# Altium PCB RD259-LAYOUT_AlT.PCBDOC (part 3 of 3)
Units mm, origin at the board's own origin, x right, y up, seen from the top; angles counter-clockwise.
Board outline 82.5 x 69.38 mm, 2 copper layers (TOP, BOTTOM), stack 0 mm thick; 80 components, 51 nets, 446 pads, 0 vias.
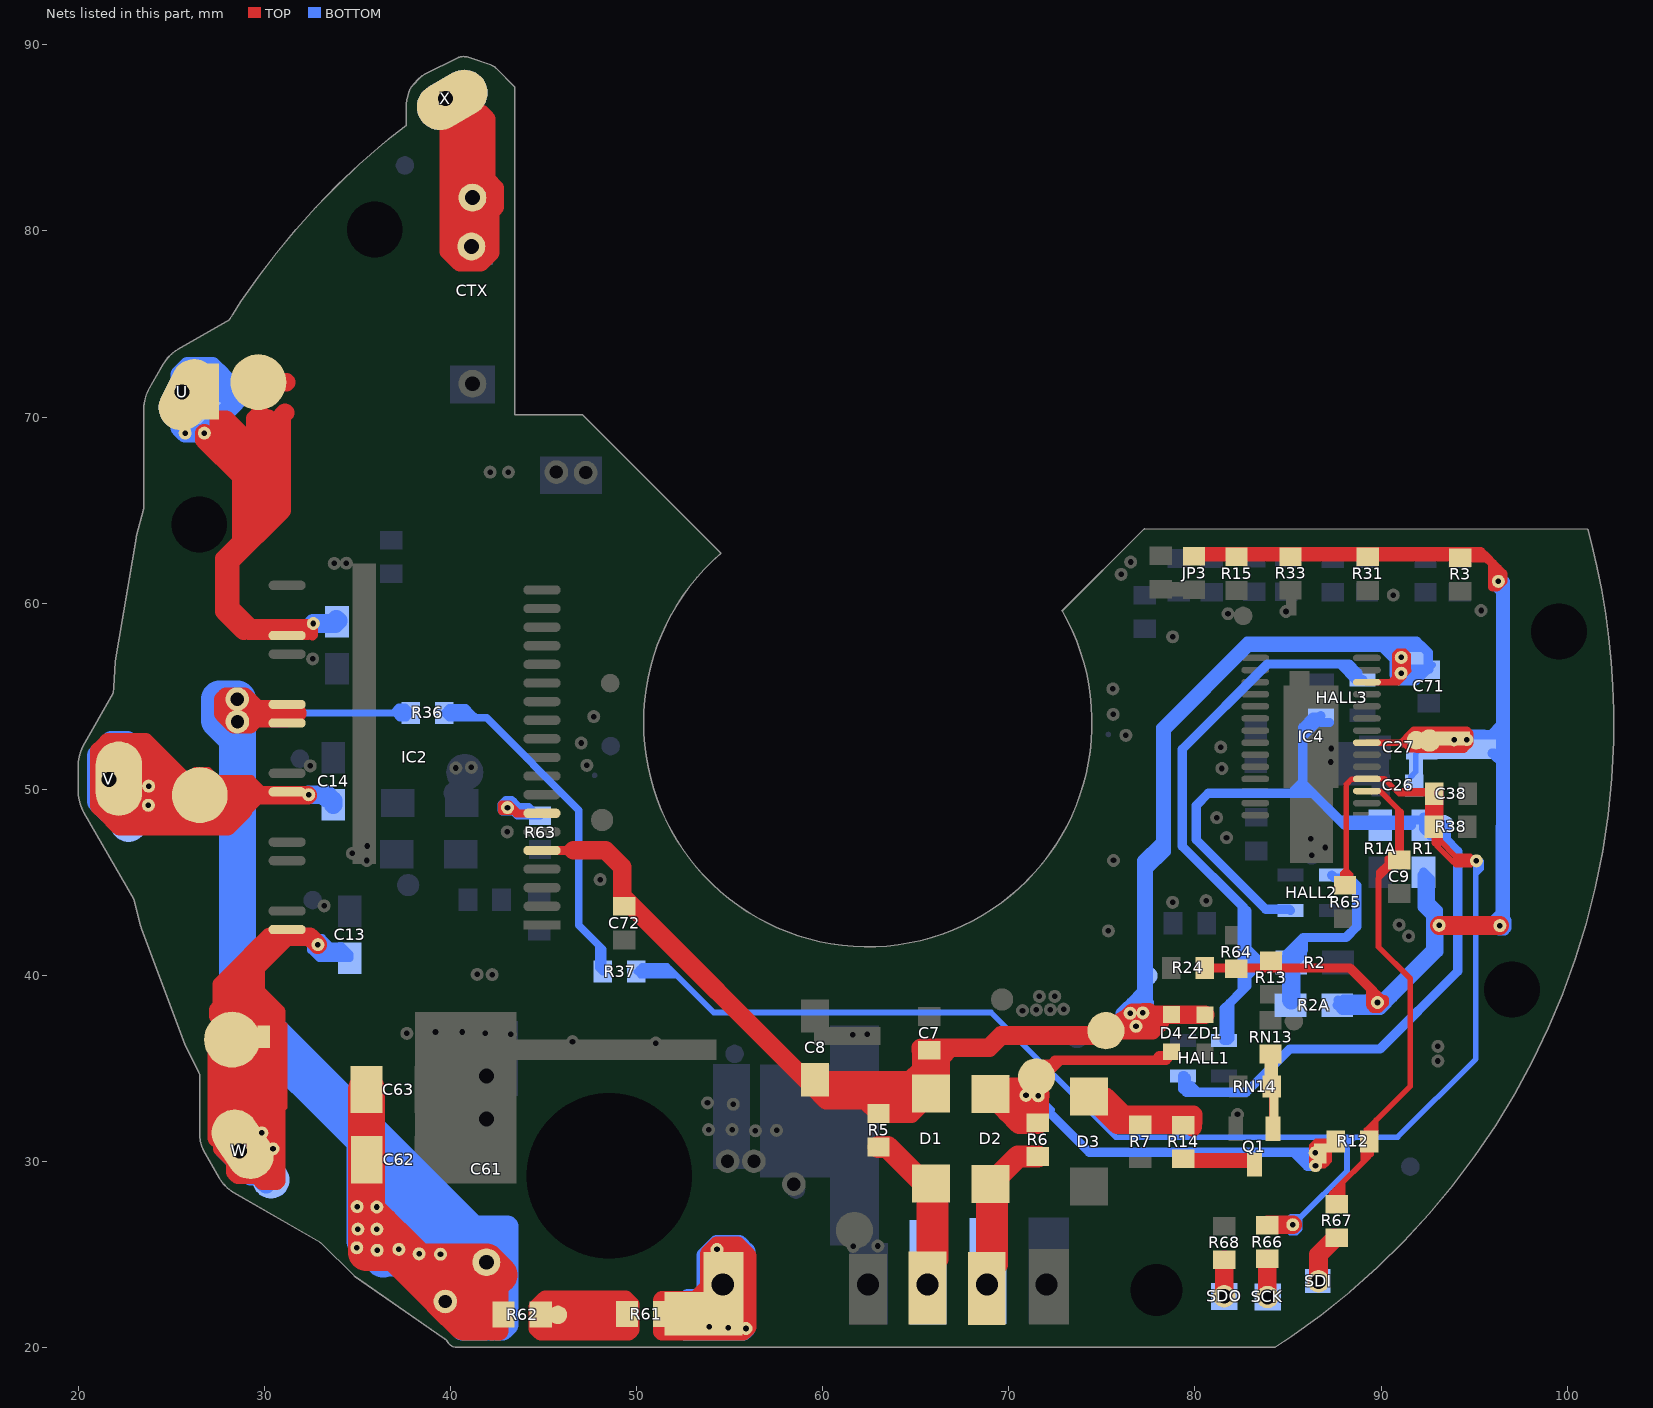
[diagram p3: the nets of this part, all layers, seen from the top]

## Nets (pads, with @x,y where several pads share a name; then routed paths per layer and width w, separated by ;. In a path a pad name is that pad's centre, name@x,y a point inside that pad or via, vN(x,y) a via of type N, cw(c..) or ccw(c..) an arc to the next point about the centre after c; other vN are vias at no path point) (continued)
NetD2_2: D2.2 D4.1 pad.@70.92,33.547 pad.@71.198,33.417 pad.@71.235,32.547 pad.@71.491,34.541 pad.@71.579,33.525 pad.@86.48,29.77 pad.@86.74,30.424 pad.@86.456,30.455 R6.2 R12.1 | length 57.1
  TOP w0.3: pad.@86.48,29.77 86.492,29.759 86.946,29.759 pad.@87.084,29.897 ; pad.@86.48,29.77 86.468,29.782 86.468,30.442 pad.@86.456,30.455 86.564,30.455 86.637,30.527 86.726,30.616 pad.@87.041,30.616 ; pad.@86.48,29.77 86.458,29.77 86.282,29.946 86.282,30.455 86.282,30.838 86.304,30.86 86.511,31.066 87.041,31.066 ; pad.@87.041,30.616 87.041,31.066 ; pad.@87.041,30.616 87.041,29.939 pad.@87.084,29.897 ; pad.@87.041,30.616 R12.1@87.222,30.616 ; 87.041,31.066 R12.1@87.572,31.066 ; pad.@87.084,29.897 87.176,29.989 87.222,30.035 R12.1@87.222,30.616 ; R12.1@87.222,30.616 87.222,30.716 R12.1@87.572,31.066 ; R12.1@87.222,30.616 87.572,30.966 R12.1@87.572,31.066
  TOP w0.5: 70.054,34.198 70.111,34.254 71.204,34.254 71.338,34.388 pad.@71.491,34.541 71.897,34.541 72.789,35.433 ; pad.@71.95,35.213 72.25,35.213 72.47,35.433 72.789,35.433 ; D4.1@78.47,35.555 78.348,35.433 ; D4.1@78.747,35.886 D4.1@78.547,35.686 ; 72.789,35.433 77.836,35.433 ; 77.836,35.433 78.088,35.686 D4.1@78.547,35.686 ; 77.836,35.433 78.348,35.433 ; 78.348,35.433 78.454,35.433 78.547,35.526 D4.1@78.547,35.686
  TOP w1.2: D2.2@69.021,33.615 D2.2@69.089,33.547 ; pad.@70.92,33.547 D2.2@69.089,33.547 ; pad.@71.338,34.388 71.338,32.83 71.202,32.693 ; pad.@71.356,33.591 pad.@71.513,33.591 ; pad.@71.579,33.591 pad.@71.513,33.591 ; D2.2@69.089,33.547 D2.2@69.943,32.693 ; D2.2@69.943,32.693 71.202,32.693 ; D2.2@69.943,32.693 70.572,32.064 ; 70.572,32.064 71.202,32.693 ; 70.572,32.064 R6.2@71.549,32.064 71.549,32.83 ; 71.202,32.693 71.413,32.693 71.549,32.83 ; pad.@71.513,33.591 pad.@71.579,33.525 71.549,33.495 71.549,32.83
  BOTTOM w0.3: pad.@70.92,33.547 70.931,33.536 71.568,33.536 71.919,33.184 ; pad.@71.153,33.047 71.197,33.003 71.785,33.003 71.801,33.003 71.986,32.819 ; pad.@71.235,32.547 71.323,32.635 72.17,32.635 ; 71.919,33.184 71.919,33.767 71.744,33.943 70.983,33.943 70.977,33.948 70.73,33.948 70.494,33.712 70.494,33.366 70.616,33.244 70.821,33.039 71.041,32.819 71.986,32.819 ; 71.919,33.184 72.327,32.777 72.185,32.635 72.17,32.635 ; 71.986,32.819 72.17,32.635
  BOTTOM w0.5: 72.17,32.635 74.313,30.491 85.281,30.491 ; 85.281,30.491 85.85,30.491 ; 85.281,30.491 86.034,29.738 86.448,29.738 pad.@86.48,29.77 ; 85.85,30.491 86.419,30.491 pad.@86.456,30.455 86.468,30.442 pad.@86.468,29.837 ; 85.85,30.491 85.85,30.455 pad.@86.468,29.837 ; pad.@86.468,29.837 86.48,29.824 pad.@86.48,29.77 ; pad.@86.468,29.837 86.468,29.782 pad.@86.48,29.77
NetD3_2: D3.2 R7.2 R14.1 | length 12.7
  TOP w1: R14.1@79.883,31.847 79.772,31.958 R7.2@77.062,31.958 75.827,31.958 D3.2@74.306,33.479 75.2,33.479 76.17,32.509 79.901,32.509 R14.1@79.901,32.086
NetHALL1_1: HALL1.1 HALL2.1 HALL3.1 pad.@82.784,40.451 R2.1 R2A.1 | length 57.1
  BOTTOM w0.5: R2.1@84.968,41.165 85.399,41.595 ; R2.1@85.077,40.451 83.3,40.451 ; HALL2.1@87.359,45.383 87.512,45.23 88.293,45.23 88.695,44.829 88.695,42.604 88.116,42.025 85.829,42.025 ; HALL3.1@89.012,55.874 HALL3.1@88.856,55.874 ; 81.865,38.5 81.573,38.209 HALL1.1@81.573,36.497 81.765,36.497 81.865,36.597 81.865,38.5 ; 81.865,38.5 82.527,39.163 ; 82.527,39.163 82.527,43.729 ; 82.527,39.163 82.784,39.419 82.784,39.935 ; 82.527,43.729 79.326,46.93 79.326,52.153 83.899,56.726 87.81,56.726 ; 82.527,43.729 82.784,43.472 82.784,41.445 ; 82.784,39.935 83.042,40.193 83.3,40.451 ; 82.784,39.935 pad.@82.784,40.451 ; pad.@82.784,40.451 82.784,40.837 ; pad.@82.784,40.451 83.3,40.451 ; 82.784,40.837 83.392,40.837 ; 82.784,40.837 82.784,41.445 ; 82.784,41.445 83.392,40.837 ; 83.392,40.837 85.019,40.837 R2.1@85.171,40.685 ; R2.1@85.171,40.685 85.386,40.685 85.771,41.07 85.771,41.285 85.829,41.343 85.829,42.025 ; R2.1@85.171,40.685 85.399,40.912 85.399,41.595 ; 85.399,41.595 85.829,42.025 ; 87.81,56.726 88.292,56.726 88.756,56.262 88.756,55.974 HALL3.1@88.856,55.874 ; 87.81,56.726 88.662,55.874 HALL3.1@88.856,55.874
  BOTTOM w1: R2A.1@85.171,38.668 R2.1@85.171,40.685
NetHALL1_3: HALL1.3 HALL2.3 HALL3.3 pad.@93.405,48.107 R1.2 R1A.2 | length 65.9
  BOTTOM w0.5: HALL2.3@85.134,43.483 85.07,43.547 83.808,43.547 80.071,47.284 80.071,49.126 80.722,49.776 85.185,49.776 ; 86.493,53.528 85.796,52.831 ; 86.761,53.589 87.232,53.589 ; HALL3.3@86.767,53.953 86.687,53.874 86.337,53.874 85.796,53.333 85.796,52.831 ; 91.637,48.052 R1A.2@89.963,48.052 88.062,48.052 87.773,48.34 ; R1.2@92.283,48.052 92.283,47.887 92.668,47.502 93.291,47.502 ; R1.2@92.292,48.5 R1.2@92.452,48.34 ; 79.531,33.707 79.348,33.89 HALL1.3@79.348,34.597 79.431,34.597 79.531,34.497 79.531,34.057 ; 79.531,33.707 79.531,34.057 ; 79.531,33.707 80.148,33.707 ; 79.531,34.057 79.798,34.057 80.148,33.707 ; 80.148,33.707 82.765,33.707 85.091,36.033 89.95,36.033 94.13,40.213 94.13,46.663 93.501,47.292 ; 85.185,49.776 85.727,50.318 85.796,50.318 ; 85.185,49.776 85.796,49.776 ; 85.796,49.776 85.796,50.318 ; 85.796,49.776 86.337,49.776 ; 85.796,50.318 85.796,52.831 ; 85.796,50.318 86.337,49.776 ; 86.337,49.776 87.773,48.34 ; 87.773,48.34 R1.2@92.452,48.34 ; R1.2@92.452,48.34 92.511,48.281 93.046,47.747 93.291,47.502 ; R1.2@92.452,48.34 93.037,48.34 93.27,48.107 pad.@93.405,48.107 93.501,48.011 93.501,47.292 ; 93.291,47.502 93.501,47.292
NetQ1_1: pad.@84.108,35.099 pad.@84.247,32.965 Q1.1 RN13.2 RN14.1 | length 4.1
  TOP w0.3: RN13.2@84.064,35.77 84.064,34.078 RN14.1@84.122,34.02 ; RN14.1@84.144,33.998 RN14.1@84.122,34.02 ; Q1.1@84.196,31.749 84.122,31.824 RN14.1@84.122,34.02
NetQ1_2: Q1.2 R14.2 | length 3.3
  TOP w0.8: R14.2@79.883,30.044 Q1.2@83.187,30.044
NetR36_2: R36.2 R37.1 | length 23.6
  BOTTOM w0.4: R36.2@39.655,54.095 41.081,54.095 ; R36.2@39.655,54.095 39.927,54.367 40.809,54.367 41.081,54.095 ; R36.2@39.655,54.095 39.915,53.835 41.341,53.835 ; 41.081,54.095 41.341,53.835 ; 41.341,53.835 41.936,53.835 46.895,48.876 46.895,42.689 47.97,41.614 ; 47.97,41.614 48.177,41.407 R37.1@48.177,40.199 47.97,40.406 47.97,41.614
NetR61_2: pad.@45.764,21.749 R61.2 R62.1 | length 16.9
  TOP w1: 46.059,22.561 45.102,22.561 44.692,22.151 44.692,21.032 44.863,20.862 49.538,20.862 49.646,20.969 49.646,22.284 49.377,22.553 45.678,22.553 45.506,22.381 45.506,22.007 pad.@45.764,21.749 48.602,21.749
RES: C38.2 IC4.4 pad.@85.259,26.594 pad.@95.129,46.15 R37.2 R38.2 R65.1 R66.1 | length 104.2
  TOP w0.3: R66.1@83.889,26.563 R66.1@83.92,26.594 ; R65.1@88.146,45.096 88.142,45.1 88.142,45.634 ; R38.2@92.837,47.983 R38.2@92.867,47.954 ; R38.2@92.858,47.983 92.867,47.974 R38.2@92.867,47.954 ; 93.285,47.114 93.187,47.211 ; 94.787,46.391 94.007,46.391 93.187,47.211 ; 94.832,45.944 94.032,45.944 93.826,46.15 ; pad.@95.129,46.15 93.826,46.15 ; 88.142,45.634 88.142,45.67 ; 88.142,45.634 88.38,45.396 88.38,45.147 R65.1@88.066,44.833 87.945,44.954 87.945,45.473 88.142,45.67 ; 88.142,45.67 88.142,50.264 88.42,50.542 89.232,50.542 IC4.4@89.242,50.552 90.186,50.552 90.813,49.925 ; 90.813,49.925 90.99,49.748 C38.2@92.858,49.748 92.681,49.925 90.813,49.925 ; R38.2@92.867,47.954 R38.2@93.072,47.749 ; R38.2@92.867,47.954 92.867,47.109 93.072,46.904 ; 93.072,46.904 93.072,47.326 ; 93.072,46.904 93.826,46.15 ; 93.072,47.326 R38.2@93.072,47.749 ; 93.072,47.326 93.187,47.211 ; R38.2@93.072,47.749 93.187,47.633 93.187,47.211
  TOP w1: R66.1@83.92,26.594 pad.@85.259,26.594 ; R38.2@92.858,47.983 C38.2@92.858,49.748
  BOTTOM w0.3: 84.941,26.803 84.973,26.835 ; pad.@85.259,26.594 85.277,26.594 85.643,26.96 ; pad.@95.101,46.15 95.101,45.444 ; pad.@95.386,46.118 95.386,45.729 95.101,45.444 ; R37.2@49.98,40.199 51.938,40.199 ; R37.2@49.98,40.199 50.197,39.983 52.155,39.983 ; R37.2@49.98,40.199 R37.2@50.133,40.352 ; R37.2@50.133,40.352 51.785,40.352 ; R37.2@50.133,40.352 50.286,40.505 51.632,40.505 51.785,40.352 ; 51.785,40.352 51.938,40.199 ; 51.938,40.199 52.155,39.983 ; 52.155,39.983 54.139,37.998 69.046,37.998 75.747,31.298 87.769,31.298 ; 84.973,26.835 84.973,26.337 84.967,26.33 84.981,26.316 85.12,26.177 85.452,26.177 85.564,26.289 85.643,26.368 85.643,26.96 ; 84.973,26.835 84.973,26.841 85.163,27.031 85.715,27.031 ; 85.643,26.96 85.715,27.031 ; 85.715,27.031 88.171,29.487 88.171,30.933 ; 87.769,31.298 88.134,30.933 88.171,30.933 ; 87.769,31.298 88.171,31.298 ; 88.171,30.933 88.171,31.298 ; 88.171,30.933 88.228,30.933 88.593,31.298 ; 88.171,31.298 88.593,31.298 ; 88.593,31.298 90.896,31.298 95.101,35.503 95.101,45.444
SCK: pad.@83.916,22.699 R66.2 SCK.1 | length 2.1
  TOP w1: R66.2@83.889,24.759 83.894,24.759 83.894,22.715 SCK.1@83.898,22.711
SD: IC2.7 pad.@43.055,49.011 R63.1 | length 12.6
  TOP w0.4: pad.@43.055,49.011 pad.@43.263,48.803 ; 43.513,48.687 44.892,48.687 IC2.7@44.911,48.706 43.636,48.706 43.539,48.803 ; pad.@43.263,48.803 42.753,48.803 42.753,49.19 42.765,49.202 43.14,49.202 43.194,49.149 43.539,48.803 ; pad.@43.263,48.803 43.539,48.803
  BOTTOM w0.4: pad.@42.974,49.011 pad.@43.055,49.011 ; pad.@43.055,49.011 43.137,49.011 43.363,48.785 ; pad.@43.055,49.011 43.113,49.068 43.657,49.068 ; 43.363,48.785 42.784,48.785 42.714,48.855 42.714,49.195 42.793,49.274 42.948,49.429 43.296,49.429 43.385,49.34 43.657,49.068 ; 43.363,48.785 44.423,48.785 R63.1@44.454,48.815 ; 43.363,48.785 43.589,48.558 44.802,48.558 R63.1@44.806,48.563 44.706,48.563 R63.1@44.454,48.815 ; 43.657,49.068 44.201,49.068 R63.1@44.454,48.815
SDI: pad.@86.606,23.574 R67.2 SDI.1 | length 2.7
  TOP w1: SDI.1@86.641,23.552 86.641,24.978 87.515,25.853 R67.2@87.515,25.895
SDO: pad.@81.576,22.744 R68.2 SDO.1 | length 2
  TOP w1: R68.2@81.57,24.71 81.573,24.71 81.573,22.75 SDO.1@81.576,22.747
TX: CTX.2 pad.@40.084,87.046 pad.@41.13,80.653 pad.@41.114,79.17 X.1 | length 36.1
  TOP w0.5: pad.@41.114,79.17 pad.@41.169,79.224
  TOP w1: X.1@39.718,87.112 pad.@39.96,87.112 ; pad.@39.784,86.894 41.169,85.51 ; 40.137,85.621 39.914,85.398 39.914,80.234 ; CTX.2@41.114,81.735 CTX.2@41.169,81.79 ; pad.@41.169,79.224 pad.@41.169,79.36 ; pad.@41.191,79.29 pad.@41.191,79.382 ; 41.631,86.297 41.924,86.004 41.924,82.731 42.017,82.639 42.369,82.287 42.369,81.293 42.129,81.053 ; 39.914,80.234 39.914,78.91 40.384,78.44 40.507,78.317 41.605,78.317 41.786,78.498 42.129,78.841 42.129,81.053 ; 39.914,80.234 40.446,79.702 ; 40.446,79.702 40.446,84.788 41.169,85.51 ; 40.446,79.702 40.979,79.17 pad.@41.114,79.17 41.114,79.305 pad.@41.169,79.36 ; pad.@41.169,79.36 pad.@41.191,79.382 ; pad.@41.169,79.36 CTX.2@41.169,81.79 ; CTX.2@41.169,81.79 41.169,85.51 ; pad.@41.191,79.382 42.077,80.269 42.077,81.002 42.129,81.053
U: ?.1 IC2.21 pad.@25.89,71.194 pad.@25.733,69.135 pad.@26.274,71.063 pad.@26.765,69.135 pad.@27.051,71.37 pad.@27.848,71.222 pad.@29.666,71.876 pad.@32.623,58.906 U.1 | length 78
  TOP w0.4: 28.877,58.506 32.011,58.506 32.354,58.849 32.566,58.849 32.617,58.9 pad.@32.623,58.906
  TOP w0.5: 28.147,60.079 28.173,60.079 29.346,58.906 ; 28.478,58.906 29.346,58.906 ; 28.877,58.506 29.127,58.256 IC2.21@31.211,58.256 32.33,58.256 32.33,58.559 pad.@32.617,58.846 ; 32.581,58.254 32.617,58.29 pad.@32.617,58.846 ; pad.@32.617,58.9 pad.@32.617,58.846 ; 29.346,58.906 pad.@32.623,58.906 32.623,58.852 pad.@32.617,58.846
  TOP w1: pad.@26.765,69.135 26.765,68.785 28.741,66.81 ; 28.877,58.506 28.478,58.906 28.147,59.237 ; pad.@29.666,71.876 31.168,71.876 ; 29.769,70.173 29.514,69.918 29.514,68.271 ; 30.205,69.907 30.232,69.879 30.232,64.757 ; 31.1,70.221 30.93,70.052 30.93,65.456 ; 28.147,59.237 28.147,60.079 28.147,62.214 ; 28.147,59.237 27.831,59.553 27.831,62.375 28.147,62.691 ; 28.147,62.214 30.93,64.998 30.93,65.456 ; 28.147,62.214 28.147,62.691 ; 28.147,62.691 28.741,63.285 ; 28.741,63.285 29.055,63.599 ; 28.741,63.285 28.741,66.81 ; 28.741,66.81 29.055,66.495 ; 29.055,63.599 29.514,64.059 ; 29.055,63.599 29.055,66.495 ; 29.055,66.495 29.514,66.036 ; 29.514,64.059 29.533,64.059 30.232,64.757 ; 29.514,64.059 29.514,66.036 ; 29.514,66.036 29.514,67.342 ; 29.514,67.342 27.546,69.31 27.546,69.859 27.926,69.859 29.514,68.271 ; 29.514,67.342 29.514,68.271 ; 30.232,64.757 30.93,65.456
  BOTTOM w1: pad.@27.848,71.222 27.848,72.062 27.56,72.35 27.303,72.607 27.195,72.715 25.873,72.715 25.443,72.284 25.443,71.338 25.443,69.426 pad.@25.733,69.135 26.274,69.135 pad.@26.765,69.135 27.483,69.854 28.35,70.72 28.455,70.825 pad.@28.455,71.332 ; pad.@32.623,58.906 33.807,58.906 ?.1@33.894,58.993 33.945,59.043 ?.1@33.861,59.127
V: C14.1 IC2.26 pad.@22.173,50.564 pad.@22.259,50.494 pad.@22.693,48.165 pad.@23.77,50.165 pad.@23.755,49.135 pad.@26.522,49.681 pad.@32.376,49.702 V.1 | length 83.3
  TOP w0.4: pad.@22.173,50.564 pad.@22.63,50.106 ; pad.@26.274,51.002 26.987,51.002 27.435,50.554 29.273,50.554 29.613,50.215 ; pad.@26.522,49.681 26.339,50.215 29.613,50.215 ; 28.545,48.858 28.857,48.858 29.169,48.858 29.992,49.681 30.069,49.758 ; 29.106,49.875 29.952,49.875 ; 30.193,49.875 29.952,49.875 ; IC2.26@31.192,49.875 IC2.26@31.211,49.856 31.229,49.856 31.275,49.81 31.275,49.803 31.396,49.681 31.509,49.568 32.182,49.568 32.213,49.538 pad.@32.346,49.405 ; IC2.26@32.16,49.837 32.255,49.741 pad.@32.376,49.741 ; 29.613,50.215 29.952,49.875
  TOP w0.5: 30.193,49.875 IC2.26@31.192,49.875
  TOP w1: pad.@22.63,50.106 24.368,50.106 ; pad.@23.755,49.135 24.218,49.599 25.723,49.599 pad.@26.522,49.681 ; 24.278,48.12 24.169,48.011 ; pad.@26.106,50.106 pad.@25.981,50.106 ; pad.@26.406,49.681 pad.@26.522,49.681 ; 28.857,48.858 28.01,48.011 24.169,48.011 ; pad.@32.316,49.681 31.396,49.681 29.992,49.681 29.106,49.681 ; pad.@21.133,51.824 21.133,49.098 21.169,49.061 ; pad.@21.133,51.824 pad.@21.169,51.824 ; pad.@21.133,51.824 21.133,52.056 21.584,52.507 22.935,52.507 ; 21.169,49.061 pad.@21.169,51.824 ; 21.169,49.061 pad.@21.372,48.858 ; pad.@21.169,51.824 21.495,52.151 22.324,52.151 23.041,51.433 24.04,50.434 24.368,50.106 ; pad.@21.372,48.858 23.12,48.858 ; pad.@21.372,48.858 22.219,48.011 24.169,48.011 ; 22.935,52.507 23.526,51.917 24.368,51.075 24.368,50.106 ; 22.935,52.507 23.58,52.507 pad.@25.981,50.106 ; 23.12,48.858 24.368,50.106 ; 23.12,48.858 28.545,48.858 29.237,49.55 29.106,49.681 ; 24.368,50.106 pad.@25.981,50.106 ; pad.@25.981,50.106 pad.@26.522,49.681 ; pad.@26.522,49.681 29.106,49.681
  BOTTOM w0.4: C14.1@33.249,49.702 33.43,49.521 C14.1@33.684,49.267
  BOTTOM w1: pad.@32.376,49.702 C14.1@33.154,49.702 ; C14.1@33.684,49.171 33.684,49.267 33.684,49.386 C14.1@33.549,49.521 ; C14.1@33.154,49.702 33.334,49.521 33.43,49.521 C14.1@33.549,49.521 ; C14.1@33.154,49.702 33.249,49.702 33.369,49.702 C14.1@33.549,49.521
  BOTTOM w1.2: pad.@21.045,51.419 21.045,49.36 21.085,49.32 21.135,49.271 21.135,49.26 pad.@22.223,48.172 ; pad.@21.046,51.419 21.046,51.795 21.772,52.521 21.772,52.53 22.612,52.53 pad.@23.183,51.959 ; pad.@22.693,48.165 pad.@22.784,48.165 ; pad.@22.784,48.165 pad.@23.183,48.564 ; pad.@22.784,48.165 23.183,48.165 pad.@23.183,48.564 ; pad.@23.183,48.564 23.686,49.067 pad.@23.755,49.135 23.755,50.656 23.816,50.718 23.816,51.326 23.454,51.689 pad.@23.183,51.959 ; pad.@23.183,48.564 pad.@23.183,51.959
VCC1: C7.1 C8.1 C71.1 C72.1 D1.2 D4.2 IC2.5 IC4.12 pad.@65.722,35.979 pad.@75.217,37.022 pad.@76.518,37.959 pad.@76.833,37.26 pad.@77.199,37.981 pad.@77.492,39.969 pad.@91.082,56.231 pad.@91.088,57.081 pad.@91.765,57.026 R5.2 ZD1.2 | length 173.5
  TOP w0.3: 46.593,46.706 46.603,46.716 ; 90.494,55.752 90.734,55.992 ; pad.@91.082,56.231 90.974,56.231 90.734,55.992 ; pad.@91.088,57.081 90.98,57.081 90.82,56.921 90.734,56.921 ; 91.155,56.671 91.095,56.611 90.734,56.611 ; 91.458,56.366 91.458,56.794 ; 90.734,55.992 90.734,56.611 ; 90.734,56.611 90.734,56.766 ; 90.734,56.766 91.155,56.766 91.43,56.766 91.458,56.794 ; 90.734,56.766 90.734,56.921 ; 90.734,56.921 90.734,57.231 90.902,57.398 91.282,57.398 91.344,57.337 91.458,57.223 91.458,56.794
  TOP w0.35: IC4.12@89.242,55.752 90.494,55.752 90.928,55.752 ; pad.@91.088,57.081 91.155,57.014 91.155,56.766 91.155,56.671 91.155,56.329 91.168,56.317 91.185,56.299 pad.@91.185,56.093 ; 91.458,56.366 pad.@91.185,56.093 ; 90.928,55.752 90.928,55.836 pad.@91.185,56.093 ; 90.928,55.752 91.185,56.009 pad.@91.185,56.093
  TOP w0.5: IC2.5@44.911,46.706 46.593,46.706
  TOP w1: 46.603,46.716 48.324,46.716 49.222,45.819 49.222,44.25 C8.1@59.533,33.939 ; C8.1@59.533,34.201 C8.1@59.533,33.939 ; C8.1@59.533,34.344 60.832,34.344 ; 61.653,33.915 62.277,33.291 ; pad.@65.722,35.979 pad.@65.414,35.979 ; pad.@76.833,37.26 77.187,37.615 ; 77.542,37.249 77.542,37.615 77.511,37.646 pad.@77.511,37.874 ; ZD1.2@80.543,37.874 77.656,37.874 ; C8.1@59.533,33.939 60.181,33.291 60.832,33.291 ; 60.832,33.291 62.277,33.291 ; 60.832,33.291 60.832,34.344 ; 60.832,34.344 62.571,34.344 ; 62.277,33.291 65.38,33.291 D1.2@65.427,33.244 ; 62.277,33.291 62.571,33.585 62.571,34.344 ; 62.277,33.291 R5.2@62.996,32.572 64.755,32.572 D1.2@65.427,33.244 ; 62.571,34.344 62.833,34.344 ; 62.833,34.344 63.306,33.87 65.306,33.87 D1.2@65.306,34.156 ; 62.833,34.344 64.686,34.344 64.902,34.56 65.306,34.965 ; D1.2@65.306,34.156 65.306,34.965 ; D1.2@65.306,34.156 D1.2@65.822,33.64 ; 65.306,34.965 65.306,35.952 65.28,35.979 pad.@65.414,35.979 ; pad.@65.414,35.979 65.822,35.571 D1.2@65.822,33.64 ; pad.@65.414,35.979 65.28,36.114 66.89,36.114 ; D1.2@65.427,33.244 D1.2@65.822,33.64 ; D1.2@65.822,33.64 66.338,34.156 66.338,35.562 66.89,36.114 ; 66.89,36.114 68.945,36.114 69.593,36.761 75.426,36.761 pad.@75.719,37.054 ; pad.@75.27,37.054 pad.@75.217,37.022 75.249,37.054 pad.@75.27,37.054 ; pad.@75.27,37.054 pad.@75.719,37.054 ; pad.@75.27,37.054 pad.@76.404,37.739 ; pad.@75.719,37.054 77.717,37.054 78.096,37.433 77.656,37.874 ; pad.@75.719,37.054 pad.@76.404,37.739 ; pad.@76.404,37.739 76.646,37.981 pad.@77.199,37.981 77.237,38.019 pad.@77.511,38.019 ; pad.@77.511,37.874 pad.@77.511,38.019 ; pad.@77.511,37.874 77.656,37.874 ; pad.@77.511,38.019 77.656,37.874
  BOTTOM w0.3: 91.432,55.829 91.681,56.078 92.117,56.078 92.217,56.078 C71.1@92.567,56.428 C71.1@92.744,56.605 ; C71.1@92.62,56.728 C71.1@92.744,56.605 ; C71.1@92.819,56.68 C71.1@92.744,56.605
  BOTTOM w0.5: pad.@76.833,37.457 pad.@76.833,37.314 ; 77.492,38.546 77.492,38.597 ; C71.1@92.567,56.428 C71.1@92.536,56.459 ; 75.976,37.488 76.551,37.488 ; 75.976,37.488 75.976,37.977 ; 75.976,37.488 76.496,36.968 77.113,36.968 77.542,37.398 pad.@77.542,38.024 ; 75.976,37.977 76.238,38.239 76.551,38.552 ; 75.976,37.977 76.062,37.977 76.299,37.74 76.551,37.488 ; 76.551,37.488 pad.@76.659,37.488 ; 76.551,37.488 76.778,37.26 pad.@76.833,37.26 ; 76.551,38.552 77.125,39.127 ; 76.551,38.552 76.551,38.138 pad.@76.597,38.092 ; pad.@76.597,38.092 76.842,38.337 77.199,38.693 77.199,38.89 ; pad.@76.597,38.092 76.624,38.065 76.794,37.895 76.794,37.624 ; pad.@76.597,38.092 76.518,38.013 pad.@76.518,37.959 76.556,37.921 76.556,37.591 pad.@76.659,37.488 ; pad.@76.659,37.488 76.794,37.624 ; pad.@76.659,37.488 pad.@76.794,37.353 ; pad.@76.794,37.353 76.794,37.624 ; pad.@76.794,37.353 pad.@76.833,37.314 ; pad.@76.794,37.353 76.794,37.299 pad.@76.833,37.26 ; pad.@76.833,37.26 pad.@76.833,37.314 ; pad.@76.833,37.26 76.871,37.299 pad.@76.871,37.353 ; pad.@76.833,37.314 pad.@76.871,37.353 ; pad.@76.871,37.353 pad.@77.542,38.024 ; pad.@76.871,37.353 76.871,37.599 76.874,37.603 77.199,37.927 pad.@77.199,37.981 77.199,38.035 77.542,38.379 ; 77.125,39.127 77.125,45.68 ; 77.125,39.127 77.125,39.058 77.199,39.058 77.199,38.89 ; 77.125,45.68 77.125,46.165 78.161,47.2 ; 77.125,45.68 77.498,46.053 ; 77.199,38.89 77.492,38.597 ; 77.492,38.597 pad.@77.492,39.969 77.498,39.976 77.498,45.67 ; 77.492,38.597 77.542,38.546 77.542,38.379 ; 77.498,45.67 77.498,46.053 ; 77.498,45.67 78.455,46.627 78.455,47.01 ; 77.498,46.053 78.161,46.715 ; pad.@77.542,38.024 77.542,38.379 ; 78.161,46.715 78.161,47.2 ; 78.161,46.715 78.455,47.01 ; 78.161,47.2 78.161,53.31 82.803,57.953 91.927,57.953 92.258,57.621 ; 78.455,47.01 78.455,53.157 82.919,57.621 90.06,57.621 ; 90.06,57.621 90.548,57.621 ; 90.06,57.621 90.703,56.978 90.703,56.121 90.996,55.829 91.432,55.829 ; 90.548,57.621 92.258,57.621 ; 90.548,57.621 pad.@91.088,57.081 91.085,57.078 91.085,56.235 pad.@91.082,56.231 91.136,56.231 pad.@91.363,56.459 ; pad.@91.363,56.459 pad.@92.497,56.459 ; pad.@91.363,56.459 91.432,56.39 91.432,55.829 ; 91.432,55.829 91.867,55.829 92.117,56.078 pad.@92.497,56.459 ; 92.258,57.621 92.536,57.343 C71.1@92.536,56.459 ; pad.@92.497,56.459 C71.1@92.536,56.459
VCC+15V: D1.1 pad.@65.626,23.189 pad.@65.628,23.378 pad.@65.658,24.037 pad.@65.764,26.235 R5.1 | length 12.9
  TOP w1: D1.1@65.628,28.619 66.266,27.981 pad.@66.266,24.739
  TOP w1.2: R5.1@62.996,30.769 63.478,30.769 65.628,28.619 pad.@65.628,23.378
Vm: pad.@53.587,21.808 pad.@53.908,21.109 pad.@54.93,21.055 pad.@54.246,21.712 pad.@54.315,25.264 pad.@54.628,23.378 pad.@54.662,23.21 pad.@54.669,23.252 pad.@55.506,25.249 pad.@55.874,21.017 R61.1 | length 39.6
  TOP w1: pad.@52.031,21.749 52.998,21.749 53.322,22.073 pad.@53.894,22.644 ; pad.@53.474,22.225 pad.@53.894,22.644 ; pad.@53.597,22.941 pad.@53.894,23.238 ; pad.@54.19,22.941 pad.@54.561,23.311 ; pad.@53.894,22.644 pad.@53.894,23.238 ; pad.@53.894,22.644 pad.@54.561,23.311 ; pad.@53.894,23.238 53.894,25.019 54.323,25.449 55.404,25.449 55.944,24.909 55.944,21.113 55.861,21.031 55.692,20.862 54.93,20.862 51.376,20.862 51.376,22.521 53.178,22.521 pad.@53.894,23.238 ; pad.@53.894,23.238 54.035,23.378 pad.@54.628,23.378 pad.@54.561,23.311
  BOTTOM w1: pad.@54.628,23.378 pad.@53.723,24.283 ; pad.@53.723,24.283 53.723,23.066 53.307,22.651 53.283,22.627 52.772,22.627 52.495,22.351 52.495,20.979 52.612,20.862 54.669,20.862 55.721,20.862 pad.@55.874,21.017 pad.@55.874,21.017 55.874,25.157 55.49,25.541 54.338,25.541 54.189,25.391 53.723,24.925 pad.@53.723,24.283
VM+310V: C61.1 C62.1 C63.1 IC2.23 IC2.24 pad.@28.53,54.838 pad.@28.542,53.629 pad.@34.957,25.355 pad.@34.976,27.566 pad.@35.015,26.355 pad.@36.034,26.355 pad.@36.034,27.547 pad.@36.053,25.22 pad.@37.22,25.268 pad.@37.88,27.105 pad.@37.725,25.007 pad.@38.303,25.028 pad.@39.457,25.008 pad.@39.715,22.469 pad.@40.593,22.436 pad.@40.944,23.807 pad.@41.665,21.999 R36.1 R62.2 | length 186.9
  TOP w0.4: pad.@28.53,54.838 28.765,54.838 28.817,54.787 pad.@29.059,54.545 ; pad.@28.536,54.8 pad.@28.542,54.806 ; pad.@28.542,53.629 pad.@28.613,53.557
  TOP w0.5: pad.@28.613,53.557 29.264,53.557 IC2.24@31.168,53.557 ; pad.@29.059,54.545 29.334,54.545 IC2.23@31.236,54.545
  TOP w1: pad.@28.53,54.838 pad.@28.536,54.832 ; pad.@28.542,53.629 28.536,53.635 pad.@28.536,54.079 ; 31.753,54.086 29.793,54.086 ; 42.48,20.862 42.499,20.881 42.599,20.881 42.599,23.899 ; 27.786,54.079 pad.@28.536,54.079 ; 27.786,54.079 28.371,53.493 29.2,53.493 29.264,53.557 29.793,54.086 ; 27.786,54.079 27.786,54.812 27.87,54.896 ; 27.87,54.896 pad.@28.982,54.896 ; 27.87,54.896 27.937,54.964 28.915,54.964 pad.@28.982,54.896 ; pad.@28.536,54.079 28.867,54.079 29.078,54.29 29.334,54.545 ; pad.@28.536,54.079 28.536,54.8 pad.@28.536,54.832 ; pad.@28.536,54.832 28.581,54.787 28.817,54.787 pad.@29.092,54.787 ; pad.@28.982,54.896 pad.@29.092,54.787 ; pad.@29.092,54.787 29.334,54.545 ; 29.334,54.545 29.793,54.086
  TOP w1.2: 41.803,21.374 42.215,20.962
  TOP w2: C63.1@35.477,33.858 35.477,27.354 ; pad.@39.715,22.469 41.169,22.469 42.599,23.899 ; 41.803,21.374 40.748,21.374 39.684,22.438 39.16,22.962 ; 35.477,26.645 35.477,25.096 pad.@37.026,25.096 ; 35.477,26.645 35.862,26.26 36.477,25.644 pad.@37.026,25.096 ; 35.477,26.645 35.477,27.354 ; 35.477,27.354 36.255,26.576 pad.@37.392,25.439 ; pad.@37.026,25.096 37.037,25.085 39.16,22.962 ; pad.@37.026,25.096 37.049,25.096 pad.@37.22,25.268 pad.@37.392,25.439 ; pad.@37.392,25.439 38.254,24.577 C61.1@41.921,24.577 42.599,23.899 ; 39.16,22.962 40.098,23.899 42.599,23.899
  BOTTOM w0.4: pad.@28.53,53.641 28.684,53.795 pad.@28.911,53.795 ; pad.@28.53,54.838 pad.@28.673,54.695 ; 28.542,52.755 28.825,52.755 29.12,53.05 30.165,54.095 ; pad.@28.542,53.629 28.745,53.629 pad.@28.911,53.795 ; pad.@28.673,54.695 29.565,54.695 30.165,54.095 ; pad.@28.673,54.695 28.696,54.672 29.31,54.672 29.887,54.095 ; pad.@28.911,53.795 29.587,53.795 29.887,54.095 ; pad.@28.911,53.795 29.211,54.095 29.887,54.095 ; 29.887,54.095 30.165,54.095 ; 30.165,54.095 36.908,54.095 ; 36.908,54.095 37.214,54.401 37.552,54.401 37.852,54.101 R36.1@37.852,54.095 ; 36.908,54.095 37.023,54.095 ; 37.023,54.095 R36.1@37.852,54.095 ; 37.023,54.095 37.272,53.846 37.603,53.846 R36.1@37.852,54.095
  BOTTOM w1: 38.849,25.028 38.849,25.008 38.849,24.413 38.849,23.604 38.849,23.021 pad.@39.764,22.107
  BOTTOM w1.2: 28.969,38.794 41.261,26.502 ; 36.476,25.489 36.611,25.624 43.039,25.624 ; pad.@38.849,23.604 39.253,23.201 43.039,23.201 ; 37.185,24.404 39.363,22.226 40.627,20.962 42.787,20.962 43.039,21.214 43.039,23.201 ; 37.185,24.404 37.194,24.413 37.725,24.413 38.849,24.413 43.039,24.413 ; 37.185,24.404 36.216,24.404 35.79,24.829 35.79,25.345 35.79,26.502 36.611,26.502 37.489,26.502 41.261,26.502 ; 41.261,26.502 43.039,26.502 43.039,25.624 ; 43.039,23.201 43.039,24.413 ; 43.039,24.413 43.039,25.624
  BOTTOM w2: 36.382,24.753 35.984,25.151 35.79,25.345 35.407,25.728 35.405,25.73 35.405,27.566 35.405,31.149 ; 37.342,29.143 39.202,27.282 38.269,27.282 37.489,26.502 36.611,25.624 36.611,26.502 36.611,29.944 35.405,31.149 ; 40.373,24.596 40.526,24.596 ; 28.542,39.221 28.969,38.794 28.969,37.586 ; 28.542,39.221 28.542,52.755 ; 28.542,39.221 28.542,38.012 28.969,37.586 ; 28.542,52.755 27.589,53.708 27.589,54.845 28.523,54.845 pad.@28.53,54.838 28.53,53.641 pad.@28.542,53.629 28.542,52.755 ; 28.969,37.586 35.405,31.149
VREG: C26.1 C27.1 IC4.7 JP3.1 pad.@89.81,38.538 pad.@91.879,51.141 pad.@91.887,52.632 pad.@92.606,52.617 pad.@93.122,42.683 pad.@93.556,52.731 pad.@93.926,52.653 pad.@94.65,52.322 pad.@94.613,52.665 pad.@96.39,42.665 pad.@96.308,61.17 R1.1 R2A.2 R3.1 R13.1 R15.2 R24.2 R31.1 R33.2 R64.1 | length 148.7
  TOP w0.3: 91.163,52.502 91.214,52.502 91.353,52.502 ; pad.@91.569,52.908 pad.@91.887,52.632
  TOP w0.35: IC4.7@89.242,52.502 91.163,52.502 ; 91.214,52.502 91.576,52.139 91.866,52.139 pad.@91.921,52.194
  TOP w0.5: R24.2@80.523,40.394 84.087,40.394 88.335,40.394 89.438,39.292 ; pad.@89.81,38.538 89.772,38.576 89.772,38.958 ; 90.167,38.693 90.167,38.563 ; 91.163,52.502 91.569,52.908 91.771,53.109 pad.@92.5,53.109 ; pad.@93.122,42.683 pad.@93.131,42.674 ; pad.@93.853,52.731 pad.@93.775,52.653 ; pad.@94.471,52.804 pad.@94.472,52.805 ; pad.@94.613,53.055 94.526,52.968 94.526,52.859 pad.@94.472,52.805 ; pad.@96.308,61.17 96.27,61.208 96.27,61.85 ; pad.@96.381,42.674 pad.@96.39,42.665 ; 89.438,39.292 89.438,38.407 89.559,38.286 89.58,38.265 89.58,38.214 89.874,38.214 90.167,38.507 90.167,38.563 ; 89.438,39.292 89.772,38.958 ; 89.772,38.958 90.001,38.729 90.167,38.563 ; pad.@92.5,53.109 pad.@92.754,53.109 ; pad.@92.5,53.109 92.023,52.632 pad.@91.887,52.632 91.483,52.632 91.921,52.194 93.316,52.194 ; pad.@92.754,53.109 94.601,53.109 94.734,52.976 94.734,52.487 94.441,52.194 93.316,52.194 ; pad.@92.754,53.109 92.837,53.026 92.837,52.859 92.843,52.854 93.043,52.653 pad.@93.775,52.653 ; 93.316,52.194 pad.@93.775,52.653 ; pad.@93.775,52.653 pad.@93.926,52.653 93.938,52.665 pad.@94.613,52.665 pad.@94.472,52.805 ; 95.675,62.446 R3.1@94.252,62.446 94.215,62.483 R15.2@82.238,62.483 79.988,62.483 JP3.1@79.951,62.519 80.199,62.767 95.354,62.767 95.675,62.446 ; 95.675,62.446 96,62.12 ; 96,62.12 96,60.871 96.221,60.871 96.543,61.192 96.543,61.578 96.27,61.85 ; 96,62.12 96.27,61.85
  TOP w1: pad.@93.131,42.674 pad.@96.381,42.674
  BOTTOM w0.3: pad.@91.603,50.67 91.864,50.93 91.864,51.912 C27.1@92.194,52.242
  BOTTOM w0.5: R2A.2@87.686,38.668 R2A.2@87.813,38.541 ; C27.1@91.735,52.34 91.915,52.52 92.01,52.615 93.888,52.615 pad.@93.926,52.653 ; R1.1@92.206,45.392 92.206,43.653 ; 92.261,52.89 92.322,52.951 pad.@95.556,52.951 ; R1.1@92.283,45.538 92.649,45.171 92.649,43.938 92.866,43.721 ; pad.@93.904,52.653 pad.@93.926,52.653 ; pad.@95.968,51.939 96.09,51.939 96.146,51.883 96.146,51.761 96.437,51.47 ; pad.@96.183,52.929 pad.@95.895,52.929 ; pad.@96.308,61.17 96.308,61.116 96.437,60.987 96.437,60.59 ; pad.@96.39,42.665 96.39,43.329 ; R2A.2@87.813,38.541 R2A.2@87.653,38.381 87.924,38.111 89.973,38.111 90.105,38.243 90.65,38.788 ; R2A.2@87.813,38.541 87.855,38.499 89.772,38.499 pad.@89.81,38.538 90.097,38.825 ; R2A.2@87.813,38.541 87.982,38.71 89.253,38.71 89.368,38.825 90.097,38.825 ; 90.097,38.825 90.614,38.825 90.65,38.788 ; 90.097,38.825 92.664,41.391 ; 90.65,38.788 93.096,41.234 93.096,41.823 ; 92.206,43.653 92.664,43.195 ; 92.206,43.653 92.799,43.653 92.866,43.721 ; 92.664,41.391 92.664,43.195 ; 92.664,41.391 93.096,41.823 ; 92.664,43.195 92.775,43.195 93.083,43.504 ; 92.664,43.195 pad.@93.083,42.776 ; 92.866,43.721 93.083,43.504 ; pad.@93.083,42.776 93.083,43.504 ; pad.@93.083,42.776 93.122,42.737 pad.@93.122,42.683 ; pad.@93.083,42.776 93.083,42.721 pad.@93.122,42.683 ; 93.096,41.823 93.096,42.657 pad.@93.122,42.683 ; pad.@93.926,52.653 93.932,52.659 94.606,52.659 pad.@94.613,52.665 94.667,52.665 94.93,52.929 pad.@95.895,52.929 ; pad.@95.895,52.929 96.437,53.471 ; 96.39,43.329 96.058,42.997 96.045,42.984 96.045,42.686 96.228,42.503 96.338,42.393 96.644,42.393 96.644,42.417 96.766,42.539 96.766,42.954 96.677,43.043 ; 96.39,43.329 96.39,47.993 ; 96.39,43.329 96.677,43.043 ; 96.39,47.993 96.437,48.04 96.437,51.47 ; 96.39,47.993 96.677,47.706 ; 96.437,51.47 96.437,53.471 ; 96.437,53.471 96.437,60.59 ; 96.437,60.59 96.045,60.982 96.045,61.471 96.384,61.471 96.677,61.178 96.677,47.706 ; 96.677,43.043 96.677,47.706
VSP: D2.1 pad.@68.88,24.101 pad.@68.773,26.324 pad.@68.814,23.17 pad.@68.828,23.378 R6.1 | length 13.1
  TOP w1: D2.1@69.021,28.789 69.458,28.352 pad.@69.458,24.451
  TOP w1.2: pad.@68.828,23.378 68.828,28.596 D2.1@69.021,28.789 70.492,30.26 R6.1@71.549,30.26
VSP1: C9.1 IC4.3 R12.2 R67.1 | length 38.8
  TOP w0.3: IC4.3@89.153,49.925 89.186,49.892 89.957,49.892 90.908,48.941 ; R12.2@89.275,31.251 89.158,31.251 89.017,31.11 R12.2@89.465,31.11 ; R12.2@89.678,31.369 R12.2@89.67,31.369 ; R12.2@89.692,31.251 R12.2@89.552,31.251 ; 90.35,46.283 90.35,46.014 89.871,45.536 89.871,45.191 ; R67.1@87.519,27.794 87.322,27.991 87.322,28.242 87.519,28.438 ; R67.1@87.519,27.794 87.519,28.438 ; R67.1@87.519,27.794 R67.1@87.615,27.698 R67.1@87.715,27.798 ; 87.519,28.438 87.715,28.635 ; R67.1@87.715,27.798 87.715,28.635 ; R67.1@87.715,27.798 87.94,28.023 87.94,28.86 ; 87.715,28.635 87.94,28.86 ; 87.94,28.86 89.058,29.977 ; 89.058,29.977 89.058,30.616 89.247,30.806 R12.2@89.273,30.806 ; 89.058,29.977 89.273,30.192 ; 89.273,30.192 R12.2@89.273,30.806 ; 89.273,30.192 89.465,30.384 R12.2@89.465,30.977 ; R12.2@89.273,30.806 89.273,30.963 R12.2@89.376,31.066 R12.2@89.465,30.977 ; R12.2@89.465,30.977 R12.2@89.465,31.11 ; R12.2@89.465,31.11 R12.2@89.465,31.369 ; R12.2@89.465,31.11 89.552,31.11 R12.2@89.552,31.251 ; R12.2@89.465,31.369 89.275,31.369 89.237,31.331 89.219,31.35 89.219,31.687 89.465,31.933 ; R12.2@89.465,31.369 89.465,31.933 ; R12.2@89.465,31.369 R12.2@89.67,31.369 ; 89.465,31.933 89.726,32.194 ; R12.2@89.552,31.251 R12.2@89.67,31.369 ; R12.2@89.67,31.369 89.726,31.424 89.726,32.194 ; 89.726,32.194 91.576,34.044 91.576,39.815 89.865,41.525 89.865,45.185 89.871,45.191 ; 89.871,45.191 90.876,46.196 C9.1@90.976,46.196 ; 90.908,48.941 91.087,48.763 91.087,46.307 C9.1@90.976,46.196 ; 90.908,48.941 90.908,46.264 C9.1@90.976,46.196
W: C13.1 IC2.30 pad.@28.253,36.543 pad.@28.824,30.917 pad.@29.3,30.267 pad.@29.853,31.532 pad.@29.961,36.701 pad.@30.348,28.998 pad.@30.452,30.671 pad.@32.869,41.643 W.1 | length 112.7
  TOP w0.203: pad.@28.002,30.085 27.941,30.085 27.529,30.496 27.529,31.174 27.529,32.031 28.16,32.662 28.253,32.662 28.837,32.662 29.13,32.662 29.261,32.531 29.849,31.943 29.855,31.938 29.983,31.809 30.036,31.809 30.619,32.392 31.122,32.895 31.122,37.372
  TOP w0.4: 28.973,38.402 29.362,38.013 ; IC2.30@32.008,42.437 32.369,42.075 32.802,41.643 pad.@32.869,41.643
  TOP w1: pad.@27.74,30.707 28.177,30.27 28.27,30.177 pad.@28.427,30.02 ; 28.973,38.402 28.973,40.757 ; pad.@32.869,41.643 32.436,42.075 32.369,42.075 31.084,42.075 ; 28.253,33.539 28.837,32.955 28.837,32.662 pad.@28.837,30.92 ; 28.253,33.539 28.253,34.503 ; 28.253,33.539 28.253,32.662 28.253,31.504 28.832,30.925 pad.@28.837,30.92 ; 28.253,34.503 pad.@29.261,35.511 ; 28.253,34.503 pad.@28.253,36.543 ; pad.@28.253,36.543 pad.@28.253,37.084 ; pad.@28.253,36.543 27.447,35.736 27.447,31.257 27.529,31.174 28.427,30.277 pad.@28.427,30.02 ; pad.@28.253,37.084 28.253,38.036 pad.@28.277,38.013 ; pad.@28.253,37.084 27.512,37.826 27.512,38.113 27.713,38.314 27.713,39.497 28.47,40.254 ; pad.@28.277,38.013 29.362,38.013 29.528,38.013 ; pad.@28.277,38.013 28.47,38.206 28.47,40.254 ; pad.@28.427,30.02 28.427,29.43 28.579,29.278 28.824,29.278 29.903,29.278 29.903,28.952 30.619,28.952 30.619,31.092 ; 28.47,40.254 28.973,40.757 ; pad.@28.837,30.92 29.261,30.496 pad.@29.261,31.344 ; pad.@28.837,30.92 pad.@29.261,31.344 ; 28.973,40.757 29.528,41.312 ; pad.@29.261,31.344 29.651,31.734 29.855,31.938 29.965,32.048 29.965,35.777 30.619,36.431 ; pad.@29.261,31.344 29.261,32.531 pad.@29.261,35.511 ; pad.@29.261,31.344 29.349,31.256 29.463,31.142 29.513,31.092 30.619,31.092 ; pad.@29.261,35.511 29.261,36.971 29.476,37.186 pad.@29.528,37.238 ; pad.@29.261,35.511 30.206,36.456 30.619,36.869 ; pad.@29.528,37.238 30.303,38.013 ; pad.@29.528,37.238 29.528,38.013 ; 29.528,38.013 30.303,38.013 ; 29.528,38.013 29.528,39.103 ; 29.528,39.103 30.619,38.013 ; 29.528,39.103 29.528,40.42 ; 29.528,40.42 31.084,41.975 31.084,42.075 ; 29.528,40.42 29.528,41.312 ; 29.528,41.312 30.291,42.075 31.084,42.075 ; 30.303,38.013 30.619,38.013 ; 30.619,31.092 30.619,32.392 30.619,36.431 ; 30.619,36.431 30.619,36.869 ; 30.619,36.869 30.619,38.013
  BOTTOM w0.4: pad.@32.869,41.643 32.869,41.609 pad.@32.915,41.562 ; 32.493,41.562 pad.@32.915,41.562 ; 32.493,41.562 32.493,41.771 32.617,41.895 32.728,42.006 33.098,42.006 33.165,41.939 33.542,41.562 ; 32.493,41.562 32.493,41.353 32.536,41.31 32.711,41.135 ; 32.711,41.135 33.342,41.135 ; 32.711,41.135 32.928,40.918 33.559,40.918 ; pad.@32.915,41.562 33.542,41.562 ; pad.@32.915,41.562 33.342,41.135 ; 33.342,41.135 34.3,41.135 C13.1@34.36,41.196 ; 33.342,41.135 33.559,40.918 ; 33.342,41.135 33.542,41.335 33.542,41.562 ; 33.542,41.562 33.768,41.562 ; 33.542,41.562 33.691,41.413 33.917,41.413 ; 33.559,40.918 C13.1@34.578,40.918 C13.1@34.578,40.978 ; 33.768,41.562 34.143,41.562 34.578,41.127 C13.1@34.578,40.978 ; 33.768,41.562 33.917,41.413 ; 33.917,41.413 34.143,41.413 C13.1@34.36,41.196 ; C13.1@34.36,41.196 C13.1@34.578,40.978
  BOTTOM w1: W.1@28.24,31.009 28.301,31.071 29.469,31.071 29.469,31.148 pad.@29.853,31.532 ; pad.@30.348,28.998 30.348,31.037 30.209,31.176 pad.@29.853,31.532 ; pad.@29.853,29.188 29.853,30.671 pad.@29.853,31.532 ; pad.@29.853,29.188 29.259,29.188 28.74,29.707 27.841,30.607 27.841,31.793 29.592,31.793 pad.@29.853,31.532 ; pad.@29.853,29.188 30.086,29.188 30.086,28.769 29.853,29.003 pad.@29.853,29.188
pads on no net: IC2.1 IC2.2 IC2.3 IC2.17 IC2.18 IC2.19 IC4.2 IC4.10 IC4.13 IC4.22

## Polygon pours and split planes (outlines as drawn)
U on TOP "TOP1" (solid, pour order 0): 24.276,68.212 23.874,68.614 23.874,70.454 23.943,70.925 23.946,70.934 24.123,71.361 24.368,71.797 24.634,72.259 24.873,72.66 25.156,73.04 25.537,73.322 25.966,73.579 27.079,74.221 30.956,74.221 32.022,73.155 32.022,69.767 31.426,69.247 27.94,69.247 26.906,68.212
no net on Top Solder "TOPSOLDER2" (solid, pour order 0): 33.921,80.077 ccw(c35.921,80.077) 37.921,80.077 ccw(c35.921,80.077)
no net on Top Solder "TOPSOLDER3" (solid, pour order 0): 97.561,58.467 ccw(c99.561,58.467) 101.561,58.467 ccw(c99.561,58.467)
no net on Top Solder "TOPSOLDER4" (solid, pour order 0): 95.041,39.237 ccw(c97.041,39.237) 99.041,39.237 ccw(c97.041,39.237)
no net on Top Solder "TOPSOLDER5" (solid, pour order 0): 76.027,23.076 ccw(c77.927,23.076) 79.827,23.076 ccw(c77.927,23.076)
no net on Top Solder "TOPSOLDER6" (solid, pour order 0): 24.791,64.217 ccw(c26.491,64.217) 28.191,64.217 ccw(c26.491,64.217)
no net on Top Solder "TOPSOLDER7" (solid, pour order 0): 52.971,23.127 43.671,23.127 43.671,35.277 53.173,35.277 53.173,23.329
no net on Bottom Solder "BOTTOMSOLDER8" (solid, pour order 0): 33.921,80.077 ccw(c35.921,80.077) 37.921,80.077 ccw(c35.921,80.077)
no net on Bottom Solder "BOTTOMSOLDER9" (solid, pour order 0): 97.561,58.467 ccw(c99.561,58.467) 101.561,58.467 ccw(c99.561,58.467)
no net on Bottom Solder "BOTTOMSOLDER10" (solid, pour order 0): 76.027,23.076 ccw(c77.927,23.076) 79.827,23.076 ccw(c77.927,23.076)
no net on Bottom Solder "BOTTOMSOLDER11" (solid, pour order 0): 95.341,39.237 ccw(c97.041,39.237) 98.741,39.237 ccw(c97.041,39.237)
no net on Bottom Solder "BOTTOMSOLDER12" (solid, pour order 0): 53.173,35.277 53.173,23.329 53.021,23.177 43.921,23.177 43.921,35.277
no net on Bottom Solder "BOTTOMSOLDER13" (solid, pour order 0): 24.491,64.217 ccw(c26.491,64.217) 28.491,64.217 ccw(c26.491,64.217)

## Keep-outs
Keep-Out Layer:
  lines w0.1: 40.671,89.377 cw(c40.671,88.453) 40.963,89.33 42.158,88.931 cw(c41.947,88.299) 42.437,88.752 43.44,87.748 43.444,87.744 43.45,87.736 43.453,87.727 43.455,87.717 43.455,84.083 43.456,84.081 43.456,84.079 43.456,84.077 43.456,70.127 47.069,70.127 47.078,70.125 47.088,70.122 47.096,70.116 47.099,70.113 54.528,62.683 ; 40.671,89.377 ccw(c40.671,88.742) 40.387,89.31 38.6,88.417 ccw(c39.047,87.522) 38.319,88.207 37.987,87.854 ccw(c38.716,87.169) 37.754,87.444 37.659,87.112 ccw(c38.621,86.837) 37.621,86.837 37.621,85.677 36.83,85.065 36.308,84.644 35.084,83.572 33.904,82.453 32.77,81.287 31.683,80.077 30.646,78.824 29.66,77.53 28.726,76.198 28.284,75.51 28.28,75.502 28.277,75.493 28.275,75.483 28.275,75.479 28.147,75.286 28.144,75.281 28.142,75.275 28.14,75.269 28.139,75.267 28.114,75.229 25.354,73.637 25.351,73.635 25.349,73.633 25.346,73.631 25.345,73.63 25.223,73.559 25,73.386 24.802,73.186 24.63,72.963 24.56,72.841 23.739,71.418 23.629,71.155 23.556,70.879 23.518,70.596 23.518,70.454 23.518,65.088 23.104,63.583 23.103,63.576 23.102,63.569 23.102,63.562 23.102,63.559 23.097,63.538 23.095,63.527 23.096,63.516 23.098,63.505 23.1,63.5 21.98,56.871 21.98,56.862 21.981,56.853 21.983,56.843 21.984,56.839 21.9,55.476 21.877,55.159 20.221,52.291 20.112,52.027 20.038,51.752 20.001,51.469 20.001,49.836 20.001,49.835 20,49.832 20,49.829 20,49.827 20,49.683 20.038,49.4 20.112,49.125 20.221,48.862 20.293,48.739 22.974,44.093 23.357,42.627 23.357,42.624 23.358,42.617 23.359,42.61 23.361,42.604 23.374,42.568 23.377,42.556 23.379,42.551 23.381,42.546 23.384,42.54 23.385,42.538 25.749,36.216 25.753,36.209 25.757,36.202 25.762,36.196 25.765,36.193 26.466,34.783 26.518,34.672 26.518,31.506 26.518,31.504 26.518,31.362 26.555,31.083 26.627,30.81 26.734,30.549 26.804,30.426 26.805,30.425 26.806,30.422 26.807,30.419 26.809,30.417 27.56,29.116 27.561,29.113 27.562,29.111 27.634,28.989 27.807,28.764 28.008,28.564 28.233,28.391 28.356,28.32 33.004,25.636 34.828,23.834 34.83,23.831 34.835,23.824 34.841,23.817 34.847,23.812 34.86,23.803 34.862,23.802 34.865,23.799 34.868,23.797 34.871,23.795 34.873,23.794 39.581,20.518 39.588,20.514 39.595,20.511 39.603,20.509 39.607,20.508 39.642,20.489 39.709,20.443 39.77,20.39 39.823,20.329 39.846,20.296 39.847,20.293 39.849,20.288 39.851,20.282 39.854,20.277 39.893,20.213 39.996,20.113 40.121,20.042 40.259,20.003 40.331,20.002 40.333,20.001 40.337,20.001 40.341,20 40.344,20 57.037,20.001 57.047,20.002 57.056,20.005 57.065,20.009 57.07,20.011 58.475,20.011 58.479,20.009 58.488,20.005 58.498,20.002 58.508,20.001 62.363,20.001 62.373,20.002 62.382,20.005 62.391,20.009 62.396,20.011 63.783,20.011 63.788,20.009 63.797,20.005 63.806,20.003 63.816,20.001 75.337,20.001 75.347,20.002 75.356,20.005 75.365,20.009 75.37,20.011 84.289,20.011 84.295,20.011 84.307,20.012 84.318,20.015 84.329,20.02 85.166,20.567 86.775,21.736 88.324,22.983 89.81,24.305 91.228,25.699 92.575,27.162 93.848,28.69 95.043,30.279 96.159,31.926 97.191,33.626 98.138,35.375 98.996,37.168 99.765,39.002 100.442,40.872 101.025,42.773 101.513,44.701 101.906,46.651 102.2,48.618 102.397,50.597 102.496,52.583 102.496,54.23 102.454,55.535 102.369,56.837 102.241,58.136 102.072,59.431 101.86,60.719 101.606,62 101.311,63.271 101.142,63.906 101.139,63.913 101.136,63.92 101.131,63.927 101.129,63.93 101.126,63.937 101.117,63.95 101.104,63.959 101.089,63.963 77.292,63.988 77.282,63.986 77.273,63.983 77.265,63.977 72.866,59.587 ; 40.671,89.377 40.671,89.377 ; 54.529,62.683 ccw(c62.421,53.577) 72.865,59.587 ; 54.528,62.683 54.529,62.683 ; 72.865,59.587 72.866,59.587

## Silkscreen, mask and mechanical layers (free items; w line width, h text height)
Top Overlay:
  drawing of 1739 lines, arcs and shapes, not listed
  text "RD259" at 33.97,64.142 h0.89
  text "3-Phase BL Motor Driver" at 34.032,62.853 h0.53
Bottom Overlay:
  drawing of 1114 lines, arcs and shapes, not listed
